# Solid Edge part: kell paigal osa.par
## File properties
Title: kell paigal osa
Author: Stella-Marii
Template: iso metric part.par
Last saved by: Stella-Marii
Revision: 7
Application: Solid Edge
Density: 7833,000 kg/m^3
Accuracy: 0,990
Username: Stella-Marii
Document Number: 17
Material: Steel, structural
Face Style: Steel
Fill Style: ANSI32(Steel)
Virtual Style: Brushed steel
Grouping: Metals\Steel
LibraryName: Materials
Coef. of Thermal Exp: 1.3e-05
Thermal Conductivity: 32.0
Specific Heat: 481.0
Modulus of Elasticity: 199947953000.0
Poisson's Ratio: 0.29
Yield Stress: 262000766.0
Ultimate Stress: 358527364.0
Elongation: 0.0
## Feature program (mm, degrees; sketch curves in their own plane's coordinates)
sketch for "unnamed Protrusion 1" plane through (0, 0, 0) normal (0, 0, 1) x-axis (1, 0, 0)
extrude "unnamed Protrusion 1" add finite 17.308 along +normal
sketch for "ExtrudedCutout_3" plane through (0, 0, 17.308) normal (0, 0, 1) x-axis (0, 1, 0)
  circle centre (0, 0) radius 12.5
extrude "ExtrudedCutout_3" cut finite 47.3139 along -normal
thinwall "Thinwall_1"  Thickness = 1 mm
fillet "Round_6" radius 1
lofted protrusion "unnamed LoftedProtrusion 1"
pattern "unnamed Pattern 1" of "unnamed LoftedProtrusion 1"
pattern "unnamed Pattern 2"
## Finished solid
Body 1: solid body, 59 faces, 129 edges, 80 vertices.
  Faces by surface: plane 34, spline 20, cylinder 4, torus 1
  Edges by curve: line 80, spline 40, circle 9
Bounding box of the edges (mm; curved faces can reach further): 43.000 x 43.000 x 17.308, from (-21.5, -21.5, 0) to (21.5, 21.5, 17.308).
Cylindrical faces by radius (mm): R12.5 x1, R13.5 x1, R20.5 x1, R21.5 x1
Toroidal faces (ring radius, tube radius in mm): R20.5 r1 x1
Planar faces by outward normal: +y 2, +z 13, -y 2, -z 1, oblique 16
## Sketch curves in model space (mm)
line (14.5, 0, 1) -> (19.5, 0, 1)
line (20.5, 0, 1) -> (22.8414, 0, 1)
line (0, 0, 1) -> (13.5, 0, 1)
line (19.5, -0.25, 1) -> (14.5, -0.25, 1)
line (14.5, -0.25, 1) -> (14.5, 0.25, 1)
line (14.5, 0.25, 1) -> (19.5, 0.25, 1)
line (19.5, 0.25, 1) -> (19.5, -0.25, 1)
line (15.5, 0.25, 4.2884) -> (18.5, 0.25, 4.2884)
line (18.5, 0.25, 4.2884) -> (18.5, -0.25, 4.2884)
line (18.5, -0.25, 4.2884) -> (15.5, -0.25, 4.2884)
line (15.5, -0.25, 4.2884) -> (15.5, 0.25, 4.2884)
line (15.5, 0.25, 15.4799) -> (18.5, 0.25, 15.4799)
line (18.5, 0.25, 15.4799) -> (18.5, -0.25, 15.4799)
line (18.5, -0.25, 15.4799) -> (15.5, -0.25, 15.4799)
line (15.5, -0.25, 15.4799) -> (15.5, 0.25, 15.4799)
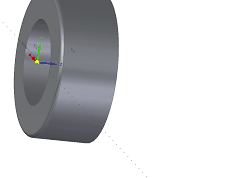
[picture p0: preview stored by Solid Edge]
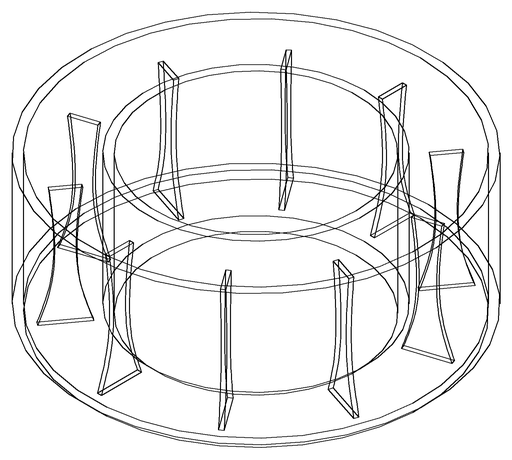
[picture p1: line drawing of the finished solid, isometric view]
